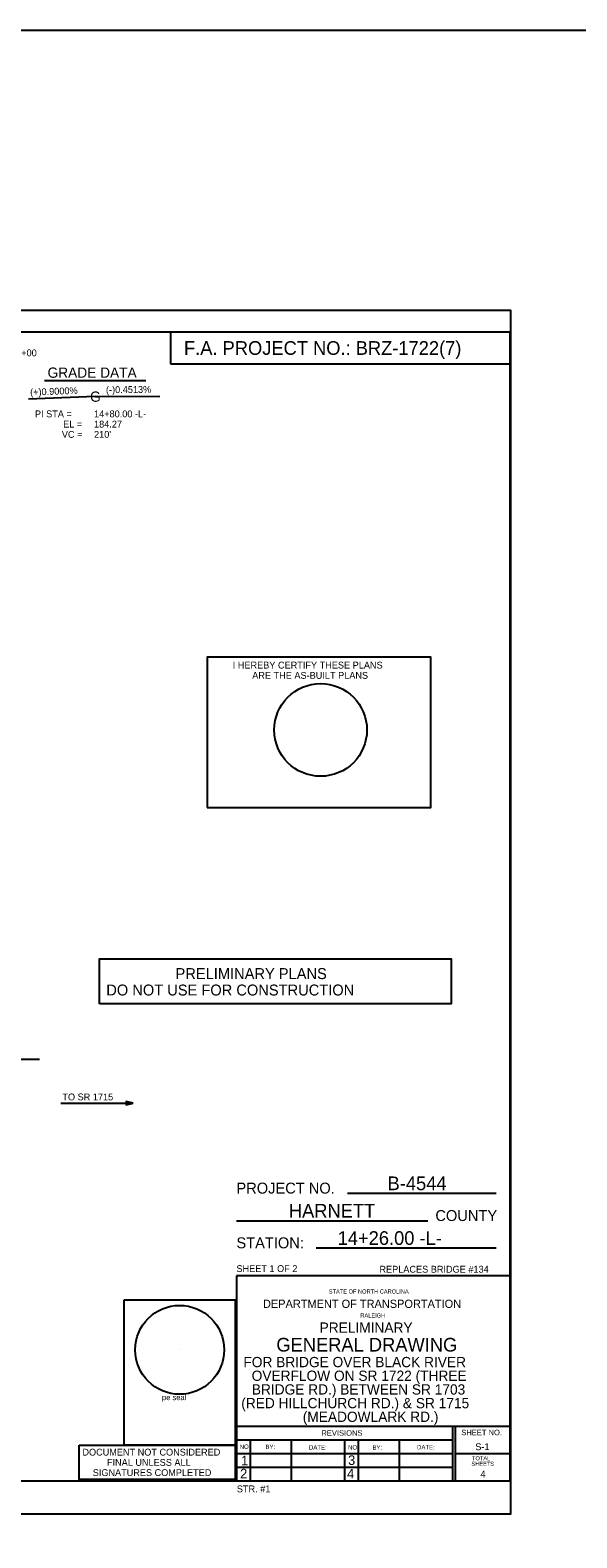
# Model space of a CAD drawing. Extents: x 471 to 2034, y -623 to 126.
# Drawn here: x 761.7 to 841.6, y -96.3 to 124.1 of the extents above; entities that cross this region are included whole.
import ezdxf

# ---------------------------------------------------------------- set-up
doc = ezdxf.new("R2010")
doc.units = 0
for name, color, linetype in [('Arrowhead Terminators CELL', 7, 'Continuous'), ('Dimension Lines', 7, 'Continuous'), ('Plan Sheet CELL', 7, 'Continuous'), ('Plot Shape CELL', 7, 'Continuous'), ('Sheet Sticker Exception Certification CELL', 7, 'Continuous'), ('Subtitle Text', 7, 'Continuous'), ('Text', 7, 'Continuous'), ('Title Text', 7, 'Continuous'), ('User Information Notes', 7, 'Continuous'), ('User Information Notes CELL', 7, 'Continuous')]:
    doc.layers.add(name, color=color, linetype=linetype)

msp = doc.modelspace()

# ---------------------------------------------------------------- linework, layer by layer
at = {"layer": 'Arrowhead Terminators CELL'}
msp.add_lwpolyline([(776.74, -32.76), (775.74, -32.51), (775.74, -33.01)], close=True, dxfattribs=at)
at = {"layer": 'Dimension Lines'}
for p, q in [((771.2, 70.54), (761.44, 70.18)), ((771.2, 70.54), (780.64, 70.62)), ((747.84, -26.33), (763.07, -26.33)), ((766.17, -32.76), (776.74, -32.76))]:
    msp.add_line(p, q, dxfattribs=at)
at = {"layer": 'Plan Sheet CELL'}
for p, q in [((831.92, 83.17), (831.92, 83.17)), ((575.85, 80.02), (831.85, 80.02)), ((782.19, 79.91), (782.19, 75.35)), ((831.85, 80.02), (831.85, -87.98)), ((782.19, 75.35), (831.85, 75.35)), ((829.85, -45.97), (808.11, -45.97)), ((819.85, -49.98), (791.85, -49.98)), ((829.85, -53.97), (803.53, -53.97)), ((831.85, -57.97), (791.85, -57.97)), ((791.85, -57.97), (791.85, -87.98)), ((791.85, -79.97), (831.85, -79.97)), ((823.45, -79.97), (823.45, -87.98)), ((823.85, -79.97), (823.85, -87.98)), ((791.85, -81.97), (823.47, -81.97)), ((791.88, -81.97), (791.88, -87.98)), ((793.85, -81.97), (793.85, -87.98)), ((799.85, -82.01), (799.85, -88.01)), ((807.66, -81.97), (807.66, -88.03)), ((809.66, -81.97), (809.66, -87.98)), ((815.66, -81.97), (815.66, -87.98)), ((791.85, -83.98), (823.53, -83.98)), ((823.85, -83.98), (831.78, -83.98)), ((575.85, -87.98), (831.85, -87.98)), ((791.85, -85.97), (823.47, -85.97)), ((831.92, -92.83), (831.92, -92.83))]:
    msp.add_line(p, q, dxfattribs=at)
for points in [[(787.56, 10.46), (820.3, 10.46), (820.3, 32.46), (787.56, 32.46)], [(771.81, -18.22), (771.81, -11.63), (823.27, -11.63), (823.27, -18.22)]]:
    msp.add_lwpolyline(points, close=True, dxfattribs=at)
at = {"layer": 'Plot Shape CELL'}
msp.add_lwpolyline([(567.42, 83.17), (831.92, 83.17), (831.92, -92.83), (567.42, -92.83)], close=True, dxfattribs=at)
at = {"layer": 'Sheet Sticker Exception Certification CELL'}
msp.add_lwpolyline([(768.86, -82.76), (791.65, -82.76), (791.65, -87.78), (768.86, -87.78)], close=True, dxfattribs=at)
at = {"layer": 'Subtitle Text'}
msp.add_line((763.78, 72.89), (778.61, 72.89), dxfattribs=at)
at = {"layer": 'User Information Notes'}
msp.add_line((820.3, 10.46), (820.3, 10.46), dxfattribs=at)
msp.add_lwpolyline([(470.96, 124.12), (1159.11, 124.12), (1159.11, -608.51), (470.96, -608.51)], close=True, dxfattribs=at)
msp.add_circle((804.16, 21.81), 6.77, dxfattribs=at)
at = {"layer": 'User Information Notes CELL'}
msp.add_line((783.55, -68.81), (783.55, -68.81), dxfattribs=at)
msp.add_lwpolyline([(775.45, -61.51), (791.65, -61.51), (791.65, -82.76), (775.45, -82.76)], close=True, dxfattribs=at)
msp.add_circle((783.55, -68.81), 6.5, dxfattribs=at)

# ---------------------------------------------------------------- texts
at = {"layer": 'Dimension Lines'}
msp.add_text('STR. #1', height=1, dxfattribs=at).set_placement((791.91, -89.64))
at = {"layer": 'Plan Sheet CELL'}
for s, height, p in [('PRELIMINARY PLANS', 1.6, (782.95, -14.61)), ('DO NOT USE FOR CONSTRUCTION', 1.6, (772.82, -17.01)), ('PROJECT NO.', 1.6, (791.85, -45.97)), ('COUNTY', 1.6, (820.94, -49.98)), ('STATION:', 1.6, (791.85, -53.97)), ('SHEET 1 OF 2', 1, (791.85, -57.44)), ('DEPARTMENT OF TRANSPORTATION', 1.2, (795.73, -62.68)), ('STATE OF NORTH CAROLINA', 0.6, (805.35, -60.58)), ('RALEIGH', 0.6, (809.97, -64.09)), ('REVISIONS', 0.8, (804.27, -81.37)), ('SHEET NO.', 0.8, (824.73, -81.29)), ('NO.', 0.637, (792.33, -83.29)), ('BY:', 0.637, (796.1, -83.32)), ('DATE:', 0.637, (802.46, -83.39)), ('NO.', 0.637, (808.17, -83.39)), ('BY:', 0.637, (811.74, -83.4)), ('DATE:', 0.637, (818.26, -83.36)), ('1', 1.4, (792.54, -85.7)), ('3', 1.4, (808.18, -85.64)), ('SHEETS', 0.6, (826.21, -85.77)), ('TOTAL', 0.6, (826.3, -84.96)), ('2', 1.4, (792.39, -87.61)), ('4', 1.4, (808.03, -87.61))]:
    msp.add_text(s, height=height, dxfattribs=at).set_placement(p)
at = {"layer": 'Sheet Sticker Exception Certification CELL'}
for s, p in [('DOCUMENT NOT CONSIDERED', (769.33, -84.27)), ('FINAL UNLESS ALL', (772.92, -85.77)), ('SIGNATURES COMPLETED', (770.84, -87.26))]:
    msp.add_text(s, height=0.9978, dxfattribs=at).set_placement(p)
at = {"layer": 'Subtitle Text'}
for s, p in [('GRADE DATA', (764.23, 73.3)), ('PRELIMINARY', (804.01, -66.31)), ('FOR BRIDGE OVER BLACK RIVER', (792.87, -71.35)), ('OVERFLOW ON SR 1722 (THREE', (794.08, -73.35)), ('BRIDGE RD.) BETWEEN SR 1703', (794.1, -75.35)), ('(RED HILLCHURCH RD.) & SR 1715', (792.56, -77.35)), ('(MEADOWLARK RD.)', (801.55, -79.35))]:
    msp.add_text(s, height=1.5, dxfattribs=at).set_placement(p)
at = {"layer": 'Text'}
for s, height, p in [('15+00', 1, (758.9, 76.44)), ('G ', 1.5, (770.45, 69.79)), ('PI STA =', 1, (762.39, 67.52)), ('14+80.00 -L-', 1, (771.03, 67.52)), ('EL =', 1, (766.51, 66.02)), ('184.27', 1, (771.03, 66.02)), ('VC =', 1, (766.32, 64.52)), ("210'", 1, (771.03, 64.52)), ('I HEREBY CERTIFY THESE PLANS', 1, (791.31, 30.79)), ('ARE THE AS-BUILT PLANS', 1, (794.16, 29.29)), ('TO SR 1715', 1, (766.4, -32.34)), ('REPLACES BRIDGE #134', 1, (812.76, -57.53)), ('S-1', 1, (826.78, -83.48)), ('4', 1, (827.53, -87.48))]:
    msp.add_text(s, height=height, dxfattribs=at).set_placement(p)
for s, rotation, p in [('(+)0.9000%', 2.1412, (761.7, 70.69)), ('(-)0.4513%', 0.4487, (772.78, 71.05))]:
    msp.add_text(s, height=1, rotation=rotation, dxfattribs=at).set_placement(p)
at = {"layer": 'Title Text'}
for s, p in [('F.A. PROJECT NO.: BRZ-1722(7)', (784.18, 76.65)), ('B-4544', (813.95, -45.47)), ('HARNETT', (799.52, -49.48)), ('14+26.00 -L-', (806.65, -53.47)), ('GENERAL DRAWING', (797.69, -69.06))]:
    msp.add_text(s, height=2, dxfattribs=at).set_placement(p)
at = {"layer": 'User Information Notes CELL'}
msp.add_text('pe seal', height=0.8, dxfattribs=at).set_placement((780.96, -76.17))

doc.saveas('drawing.dxf')
